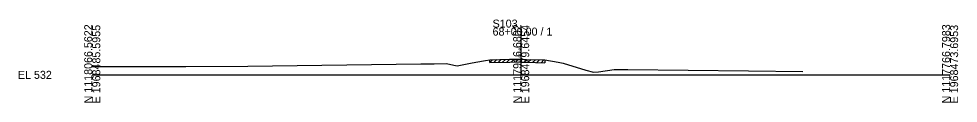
# Model space of a CAD drawing. Extents: x 974 to 1303, y 990 to 14518.
# Drawn here: x 974.3 to 1302.8, y 10490.3 to 10519.4 of the extents above; entities that cross this region are included whole.
import ezdxf

# ---------------------------------------------------------------- set-up
doc = ezdxf.new("R2010")
doc.units = 0
for name, color, linetype in [('Level 10', 7, 'Continuous'), ('Level 60', 7, 'Continuous'), ('Level 61', 7, 'Continuous'), ('Level 63', 7, 'Continuous')]:
    doc.layers.add(name, color=color, linetype=linetype)

msp = doc.modelspace()

# ---------------------------------------------------------------- linework, layer by layer
at = {"layer": 'Level 60'}
for p, q in [((1054.43, 10503.07), (1114.87, 10503.84)), ((1114.87, 10503.84), (1119.53, 10503.83)), ((1119.53, 10503.83), (1123.88, 10503.99)), ((1123.88, 10503.99), (1126.48, 10503.42)), ((1126.48, 10503.42), (1127.59, 10503.13)), ((1127.59, 10503.13), (1132.3, 10504.03)), ((1132.3, 10504.03), (1134.18, 10504.41)), ((1134.18, 10504.41), (1137.47, 10505.03)), ((1137.47, 10505.03), (1138.99, 10505.29)), ((1138.99, 10505.29), (1146.08, 10505.45)), ((1146.08, 10505.45), (1148.94, 10505.51)), ((1148.94, 10505.51), (1150, 10505.48)), ((1150, 10505.48), (1151.79, 10505.42)), ((1151.79, 10505.42), (1158.3, 10505.2)), ((1158.3, 10505.2), (1162.96, 10504.38)), ((1162.96, 10504.38), (1164.63, 10504.09)), ((1164.63, 10504.09), (1172.66, 10501.66)), ((1000, 10502.92), (1032.73, 10502.9)), ((1032.73, 10502.9), (1054.43, 10503.07)), ((1172.66, 10501.66), (1175.25, 10500.96)), ((1175.25, 10500.96), (1177.06, 10501.11)), ((1177.06, 10501.11), (1182.53, 10501.9)), ((1182.53, 10501.9), (1187.34, 10501.89)), ((1187.34, 10501.89), (1229.52, 10501.41)), ((1229.52, 10501.41), (1248.45, 10501.22))]:
    msp.add_line(p, q, dxfattribs=at)
at = {"layer": 'Level 61'}
for p, q in [((1138.99, 10504.29), (1140.02, 10505.31)), ((1138.99, 10504.29), (1138.99, 10505.29)), ((1138.99, 10504.29), (1146.08, 10504.45)), ((1138.99, 10504.29), (1138.99, 10504.29)), ((1140.49, 10504.32), (1141.52, 10505.35)), ((1141.99, 10504.36), (1143.02, 10505.38)), ((1143.49, 10504.39), (1144.52, 10505.42)), ((1144.99, 10504.43), (1146.02, 10505.45)), ((1146.08, 10504.45), (1148.94, 10504.51)), ((1146.49, 10504.46), (1147.51, 10505.48)), ((1147.99, 10504.49), (1149.01, 10505.51)), ((1148.94, 10504.51), (1150, 10504.48)), ((1149.49, 10504.5), (1150.46, 10505.46)), ((1150, 10504.48), (1151.79, 10504.42)), ((1150.99, 10504.45), (1151.96, 10505.41)), ((1151.79, 10504.42), (1158.3, 10504.2)), ((1152.49, 10504.4), (1153.46, 10505.36)), ((1153.99, 10504.35), (1154.96, 10505.31)), ((1155.49, 10504.3), (1156.46, 10505.26)), ((1156.99, 10504.25), (1157.96, 10505.22)), ((1158.3, 10505.2), (1158.3, 10504.2))]:
    msp.add_line(p, q, dxfattribs=at)
at = {"layer": 'Level 63'}
for p, q in [((1150, 10500), (1150, 10516.54)), ((1000, 10500), (1150, 10500)), ((1150, 10500), (1300, 10500))]:
    msp.add_line(p, q, dxfattribs=at)

# ---------------------------------------------------------------- texts
at = {"layer": 'Level 10'}
msp.add_text('537.48', height=0.9, rotation=90, dxfattribs=at).set_placement((1149.95, 10505.98))
at = {"layer": 'Level 63'}
for s, p in [('N 1118066.5622', (1000, 10490)), ('E 1968485.5955', (1002.8, 10490)), ('N 1117916.6802', (1150, 10490)), ('E 1968479.6454', (1152.8, 10490)), ('N 1117766.7983', (1300, 10490)), ('E 1968473.6953', (1302.8, 10490))]:
    msp.add_text(s, height=2.8, rotation=90, dxfattribs=at).set_placement(p)
for s, p in [('S103', (1140, 10516.54)), ('68+00.00 / 1', (1140, 10513.74)), ('EL 532', (974, 10498.6))]:
    msp.add_text(s, height=2.8, dxfattribs=at).set_placement(p)

doc.saveas('drawing.dxf')
